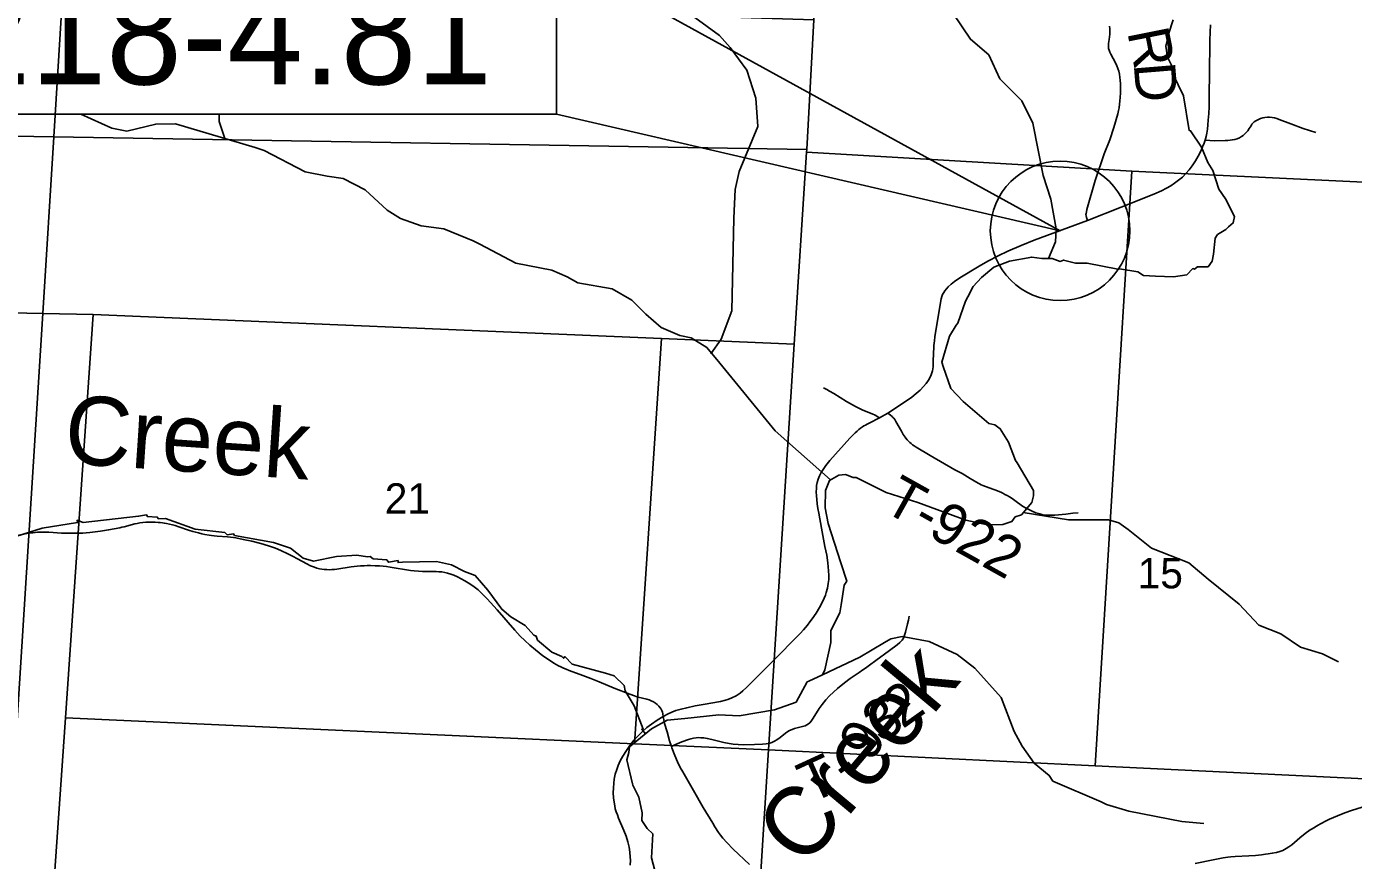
# Model space of a CAD drawing. Extents: x 0 to 34, y 0 to 22.
# Drawn here: x 2.913 to 4.739, y 15.408 to 16.555 of the extents above; entities that cross this region are included whole.
import ezdxf

# ---------------------------------------------------------------- set-up
doc = ezdxf.new("R2010")
doc.units = 0
for name, color, linetype in [('Default', 7, 'Continuous'), ('GM_X_County_Road', 7, 'Continuous'), ('GM_X_Minor_River', 7, 'Continuous'), ('GM_X_Minor_River_Text', 7, 'Continuous'), ('GM_X_Section', 7, 'Continuous'), ('GM_X_Section_Text', 7, 'Continuous'), ('GM_X_State_Route', 7, 'Continuous'), ('GM_X_Township_Road', 7, 'Continuous'), ('GM_X_Township_Road_Text', 7, 'Continuous'), ('TX_P_1', 7, 'Continuous')]:
    doc.layers.add(name, color=color, linetype=linetype)

msp = doc.modelspace()

# ---------------------------------------------------------------- linework, layer by layer
at = {"layer": 'Default'}
for points in [[(2.1, 16.6219), (2.1, 16.4177), (2.9504, 16.4035), (2.9626, 16.5982)], [(2.1, 16.4177), (2.1, 16.178), (2.4468, 16.1708), (2.9352, 16.1608), (2.9504, 16.4035)]]:
    msp.add_lwpolyline(points, close=True, dxfattribs=at)
at = {"layer": 'GM_X_County_Road'}
for points in [[(2.9754, 15.8582), (2.9804, 15.8581), (2.9906, 15.8583), (2.9951, 15.8586), (2.9999, 15.8592), (3.0145, 15.861), (3.0202, 15.8618), (3.0259, 15.8628), (3.0415, 15.8658), (3.0443, 15.8664), (3.0474, 15.8672), (3.0619, 15.871), (3.0653, 15.8717), (3.069, 15.8724), (3.0729, 15.8729), (3.0769, 15.8733), (3.0812, 15.8735), (3.0857, 15.8735), (3.0901, 15.8734), (3.0939, 15.8732), (3.0969, 15.873), (3.0999, 15.8727), (3.1024, 15.8723), (3.1053, 15.8717), (3.1096, 15.8708), (3.1137, 15.8698), (3.1175, 15.8688), (3.1226, 15.8672), (3.136, 15.8626), (3.1419, 15.8607), (3.1457, 15.8596), (3.1497, 15.8586), (3.1541, 15.8576), (3.1583, 15.8567), (3.1642, 15.8557), (3.1676, 15.8551), (3.1712, 15.8547), (3.1752, 15.8543), (3.1893, 15.8532), (3.1936, 15.8527), (3.1975, 15.8522), (3.2009, 15.8517), (3.2112, 15.8498), (3.2231, 15.8472), (3.2352, 15.8442), (3.2457, 15.841), (3.2553, 15.8375), (3.263, 15.8343), (3.2723, 15.8301), (3.2789, 15.8267), (3.2856, 15.823), (3.2984, 15.816), (3.3037, 15.8135), (3.309, 15.8114), (3.3124, 15.8103), (3.3159, 15.8094), (3.3191, 15.8088), (3.3226, 15.8083), (3.326, 15.8082), (3.3294, 15.8081), (3.3332, 15.8082), (3.3367, 15.8085), (3.3397, 15.8089), (3.3597, 15.8119), (3.3636, 15.8124), (3.3677, 15.8129), (3.3724, 15.8133), (3.3776, 15.8136), (3.3818, 15.8137), (3.3862, 15.8137), (3.3925, 15.8136), (3.3986, 15.8134), (3.4035, 15.813), (3.4082, 15.8124), (3.4133, 15.8117), (3.4187, 15.8108), (3.4359, 15.8077), (3.441, 15.807), (3.4464, 15.8063), (3.452, 15.8059), (3.4577, 15.8057), (3.4765, 15.8055), (3.4804, 15.8053), (3.4843, 15.8049), (3.4883, 15.8042), (3.4921, 15.8033), (3.4965, 15.802), (3.5009, 15.8004), (3.506, 15.7981), (3.5107, 15.7957), (3.516, 15.7928), (3.5227, 15.7886), (3.5287, 15.7845), (3.5341, 15.7802), (3.5395, 15.7753), (3.5466, 15.768), (3.5604, 15.7529), (3.5847, 15.7249), (3.5923, 15.7167), (3.5985, 15.7105), (3.6053, 15.7041), (3.613, 15.6977), (3.6233, 15.6897), (3.6309, 15.6843), (3.6383, 15.6795), (3.6448, 15.6758), (3.6481, 15.6743), (3.6518, 15.6726), (3.6555, 15.6711), (3.6595, 15.6695), (3.6785, 15.6626), (3.6892, 15.6585), (3.7009, 15.6538), (3.7214, 15.6452), (3.7431, 15.6366), (3.7493, 15.6344), (3.7518, 15.6336), (3.7545, 15.6328), (3.7662, 15.6299), (3.7694, 15.6289), (3.7725, 15.6278), (3.7755, 15.6263), (3.7781, 15.6246), (3.7805, 15.6227), (3.7827, 15.6204), (3.7845, 15.6182), (3.7859, 15.616), (3.7869, 15.6141), (3.7877, 15.6119), (3.7884, 15.6095), (3.789, 15.6059)], [(2.896, 15.8544), (2.9157, 15.8581), (2.9188, 15.8586), (2.9217, 15.859), (2.925, 15.8594), (2.9282, 15.8596), (2.9325, 15.8598), (2.9369, 15.8598), (2.9404, 15.8598), (2.9438, 15.8596), (2.9613, 15.8585), (2.9754, 15.8582)], [(4.5208, 15.4038), (4.5455, 15.4088), (4.5594, 15.4114), (4.5655, 15.4125), (4.5698, 15.413), (4.5759, 15.4136), (4.5945, 15.4143), (4.6038, 15.4149), (4.6119, 15.4159), (4.6174, 15.4166), (4.6211, 15.4171), (4.6268, 15.418), (4.6324, 15.4191), (4.6372, 15.4204), (4.6413, 15.4219), (4.6458, 15.4242), (4.6496, 15.4265), (4.6536, 15.4295), (4.6648, 15.4392), (4.6721, 15.4449), (4.6791, 15.4499), (4.6816, 15.4516), (4.6899, 15.4567), (4.6931, 15.4584), (4.6958, 15.4599), (4.699, 15.4615), (4.7056, 15.4649), (4.7164, 15.4695), (4.7268, 15.4734), (4.7356, 15.4765), (4.7504, 15.4814)]]:
    msp.add_lwpolyline(points, dxfattribs=at)
at = {"layer": 'GM_X_Minor_River'}
for points in [[(4.3191, 16.2364), (4.3286, 16.2594), (4.3296, 16.2772), (4.3221, 16.3181), (4.3114, 16.3507), (4.2973, 16.4225), (4.2824, 16.453), (4.2655, 16.4703), (4.2519, 16.4836), (4.2367, 16.5167), (4.2116, 16.538), (4.1877, 16.5733), (4.0987, 16.692), (4.0621, 16.7448), (4.0288, 16.766), (4.0171, 16.7789), (4.0136, 16.7881), (4.0099, 16.7928), (3.9283, 16.8675), (3.9083, 16.905)], [(3.8542, 16.1051), (3.8688, 16.1253), (3.8834, 16.1644), (3.886, 16.2916), (3.8881, 16.3311), (3.8932, 16.3562), (3.919, 16.4179), (3.9165, 16.457), (3.9038, 16.4956), (3.8812, 16.5266), (3.8663, 16.5429), (3.8324, 16.5681), (3.7246, 16.6317), (3.6823, 16.6516), (3.5724, 16.6992), (3.485, 16.7682), (3.469, 16.7784), (3.39, 16.8007), (3.374, 16.8086), (3.3423, 16.8328)], [(4.4838, 16.5423), (4.4842, 16.545), (4.4906, 16.5648)], [(4.1944, 16.1473), (4.2048, 16.1776), (4.2082, 16.1837), (4.2153, 16.1977), (4.2267, 16.2099), (4.2437, 16.2244), (4.2652, 16.2324), (4.2958, 16.2382), (4.3098, 16.2364), (4.3238, 16.2364), (4.3348, 16.2322), (4.3397, 16.2341), (4.3559, 16.23), (4.3722, 16.2297), (4.4142, 16.2214), (4.4168, 16.2222), (4.4418, 16.218), (4.4497, 16.2127), (4.466, 16.212), (4.4909, 16.2109), (4.5094, 16.214), (4.5177, 16.2224), (4.52, 16.2217), (4.5238, 16.2247), (4.5385, 16.2247), (4.5442, 16.2327), (4.5461, 16.2422), (4.5483, 16.2643), (4.5513, 16.2692), (4.563, 16.2761), (4.5664, 16.2799), (4.5732, 16.2852), (4.5747, 16.294), (4.5626, 16.3183), (4.5535, 16.3319), (4.5452, 16.3574), (4.538, 16.3684), (4.5293, 16.3893), (4.5145, 16.412), (4.5123, 16.4124), (4.5047, 16.4603), (4.4899, 16.4903), (4.488, 16.5021), (4.4827, 16.5131), (4.4804, 16.5286), (4.4838, 16.5423)], [(4.0192, 15.9318), (3.9431, 15.9991), (3.8666, 16.0922), (3.8491, 16.1137), (3.8272, 16.1273), (3.8118, 16.1304), (3.786, 16.1411), (3.7651, 16.1596), (3.7456, 16.1788), (3.7185, 16.1945), (3.6715, 16.2028), (3.6566, 16.2109), (3.6357, 16.2203), (3.5861, 16.2298), (3.5367, 16.2561), (3.5274, 16.2605), (3.487, 16.277), (3.4558, 16.281), (3.4274, 16.2914), (3.4092, 16.303), (3.3787, 16.3309), (3.3485, 16.3463), (3.3267, 16.3496), (3.2963, 16.3555), (3.2397, 16.385), (3.2274, 16.3888), (3.118, 16.4215), (3.0908, 16.4213), (3.0508, 16.4115), (3.0305, 16.4156), (2.9876, 16.4348)], [(3.1856, 16.4013), (3.1782, 16.4249), (3.1782, 16.4348)], [(3.972, 15.626), (3.9871, 15.6537), (3.9894, 15.6545), (4.0079, 15.6633), (4.0113, 15.6705), (4.0196, 15.7078), (4.0196, 15.7245), (4.032, 15.7485), (4.0335, 15.7599), (4.038, 15.7869), (4.0414, 15.7922), (4.0331, 15.8173), (4.0157, 15.8716), (4.0119, 15.8932), (4.0122, 15.9172), (4.0175, 15.9308), (4.0307, 15.9381), (4.0398, 15.9389), (4.0504, 15.9351), (4.0545, 15.9351), (4.0954, 15.9143), (4.1392, 15.9004), (4.205, 15.8762), (4.2349, 15.8698), (4.2561, 15.8702), (4.2686, 15.8745), (4.2731, 15.8809), (4.2818, 15.8836), (4.2961, 15.9007), (4.2984, 15.9095), (4.2984, 15.9171), (4.2757, 15.955), (4.2734, 15.9581), (4.2639, 15.9835), (4.2526, 16.0021), (4.245, 16.0074), (4.2367, 16.0093), (4.2015, 16.0396), (4.1848, 16.0574), (4.1739, 16.0878), (4.1723, 16.0935), (4.1829, 16.1296), (4.1919, 16.1445), (4.1944, 16.1473)], [(3.7645, 15.5823), (3.7593, 15.5885), (3.7615, 15.5885), (3.749, 15.6208), (3.7365, 15.6413), (3.735, 15.6485), (3.7214, 15.6618), (3.7093, 15.6659), (3.6635, 15.678), (3.6537, 15.6886), (3.6518, 15.6863), (3.6492, 15.6886), (3.6355, 15.6946), (3.6159, 15.7113), (3.614, 15.7166), (3.611, 15.7181), (3.5988, 15.7314), (3.5792, 15.7431), (3.5667, 15.7537), (3.5478, 15.7799), (3.5304, 15.8), (3.5156, 15.8056), (3.4978, 15.8147), (3.477, 15.8192), (3.4302, 15.8183), (3.4241, 15.8179), (3.4241, 15.8206), (3.4109, 15.8183), (3.4086, 15.8217), (3.3897, 15.8232), (3.3859, 15.8262), (3.3822, 15.8258), (3.3674, 15.828), (3.3394, 15.8261), (3.3077, 15.8199), (3.2937, 15.824), (3.2759, 15.8377), (3.2529, 15.8456), (3.1992, 15.8553), (3.1977, 15.8576), (3.189, 15.8561), (3.1856, 15.8591), (3.1451, 15.8639), (3.1043, 15.8783), (3.0944, 15.8782), (3.0929, 15.8805), (3.0793, 15.8812), (3.0782, 15.8835), (3.0672, 15.8816), (2.9909, 15.873), (2.9826, 15.876), (2.9833, 15.873), (2.9346, 15.8653), (2.8896, 15.8511)], [(4.2843, 15.8867), (4.3465, 15.8769), (4.4013, 15.8767), (4.4155, 15.8724), (4.4285, 15.8636), (4.4606, 15.8379), (4.5122, 15.8177), (4.5387, 15.7952), (4.5811, 15.7608), (4.6082, 15.7318), (4.6388, 15.7199), (4.6655, 15.7015), (4.6958, 15.6922), (4.7178, 15.6813)], [(4.0079, 15.6633), (4.0596, 15.6878), (4.0934, 15.708), (4.1019, 15.713), (4.1175, 15.716), (4.1547, 15.7091), (4.1931, 15.6912), (4.2178, 15.6725), (4.254, 15.6323), (4.2719, 15.5854), (4.2826, 15.5653), (4.2993, 15.542), (4.32, 15.525), (4.325, 15.5172), (4.3914, 15.4885), (4.3989, 15.4849), (4.4296, 15.4759), (4.5025, 15.4618), (4.5327, 15.4589)], [(3.7944, 15.6012), (3.8186, 15.6035), (3.8655, 15.6082), (3.8934, 15.6071), (3.9418, 15.6152), (3.972, 15.626)], [(3.7791, 15.3875), (3.7726, 15.4115), (3.7745, 15.4445), (3.7666, 15.4521), (3.7594, 15.4631), (3.7601, 15.4734), (3.7552, 15.495), (3.7472, 15.5117), (3.7465, 15.5136), (3.7389, 15.5463), (3.7415, 15.5566), (3.7426, 15.5642), (3.7729, 15.5893), (3.7944, 15.6012)]]:
    msp.add_lwpolyline(points, dxfattribs=at)
at = {"layer": 'GM_X_Section'}
for points in [[(4.0444, 17.3771), (5.0921, 17.3266), (5.0662, 16.9077), (5.041, 16.4863), (5.0334, 16.328), (4.4335, 16.3564), (3.9862, 16.3827), (3.9864, 16.3863), (3.9959, 16.5649), (4.0188, 16.9784)], [(2.9626, 16.5982), (3.9959, 16.5649), (3.9864, 16.3863), (2.9504, 16.4035)], [(3.9864, 16.3863), (3.9862, 16.3827), (3.9691, 16.1182), (3.7866, 16.126), (3.0046, 16.1593), (2.9352, 16.1608), (2.9504, 16.4035)], [(4.4335, 16.3564), (4.383, 15.5384), (3.9339, 15.5602), (3.9691, 16.1182), (3.9862, 16.3827)], [(5.0334, 16.328), (5.0168, 16.0903), (4.9455, 16.091), (4.9066, 15.513), (4.383, 15.5384), (4.4335, 16.3564)], [(2.9352, 16.1608), (2.8841, 15.3459), (2.3978, 15.3611), (2.4468, 16.1708)], [(3.0046, 16.1593), (2.9664, 15.604), (2.9483, 15.3412), (2.8868, 15.3457), (2.8841, 15.3459), (2.9352, 16.1608)], [(3.7866, 16.126), (3.7495, 15.5685), (2.9664, 15.604), (3.0046, 16.1593)], [(3.9691, 16.1182), (3.9339, 15.5602), (3.7495, 15.5685), (3.7866, 16.126)], [(2.9664, 15.604), (3.7495, 15.5685), (3.9339, 15.5602), (3.9173, 15.2973), (2.9483, 15.3412)], [(3.9339, 15.5602), (4.383, 15.5384), (4.9066, 15.513), (4.889, 15.2523), (3.9173, 15.2973)]]:
    msp.add_lwpolyline(points, close=True, dxfattribs=at)
at = {"layer": 'GM_X_State_Route'}
for points in [[(3.8437, 15.6225), (3.8677, 15.6266), (3.8744, 15.6284), (3.878, 15.6295), (3.8832, 15.6316), (3.8894, 15.6347), (3.8947, 15.6382), (3.8986, 15.6413), (3.9041, 15.6464), (3.9437, 15.6864), (3.9724, 15.7152), (3.9774, 15.7204), (3.9819, 15.7251), (3.9875, 15.7319), (3.9907, 15.7361), (3.9938, 15.7404), (3.9991, 15.7481), (4.004, 15.7561), (4.0076, 15.7627), (4.0105, 15.769), (4.012, 15.7731), (4.0132, 15.7767), (4.0148, 15.7827), (4.016, 15.7889), (4.0166, 15.7945), (4.0168, 15.8002), (4.0165, 15.8064), (4.0153, 15.8176), (4.0139, 15.8281), (4.0114, 15.8402), (4.0066, 15.8651), (4.0028, 15.8859), (4.0018, 15.8922), (4.0008, 15.8985), (4.0001, 15.9047), (3.9998, 15.9096), (3.9995, 15.9151), (3.9996, 15.92), (3.9999, 15.9241), (4.0008, 15.928), (4.0022, 15.9325), (4.0041, 15.9371), (4.0063, 15.9417), (4.0089, 15.9459), (4.0128, 15.9515), (4.0182, 15.9582), (4.0456, 15.989), (4.0493, 15.9929), (4.0528, 15.9964), (4.0555, 15.9989), (4.0579, 16.0009), (4.0602, 16.0026), (4.0629, 16.0045), (4.065, 16.0059), (4.0672, 16.0071), (4.0696, 16.0084), (4.0722, 16.0097), (4.0863, 16.0168), (4.0981, 16.0233), (4.1238, 16.0402), (4.1311, 16.0456), (4.1371, 16.0505), (4.1425, 16.0553), (4.1472, 16.0601), (4.1508, 16.0643), (4.154, 16.0689), (4.1561, 16.0728), (4.1576, 16.0763), (4.1592, 16.0818), (4.1601, 16.0873), (4.1605, 16.0929), (4.1609, 16.1078), (4.1611, 16.1121), (4.1613, 16.1164), (4.1619, 16.1232), (4.1627, 16.1287), (4.1704, 16.1758), (4.1713, 16.1806), (4.1722, 16.1841), (4.1733, 16.1869), (4.1748, 16.1895), (4.1764, 16.192), (4.1786, 16.1945), (4.181, 16.1972), (4.185, 16.201), (4.1898, 16.2048), (4.197, 16.2097), (4.2234, 16.2259), (4.2353, 16.2324), (4.2497, 16.2398), (4.2631, 16.2462), (4.2813, 16.2543), (4.2991, 16.2614), (4.3724, 16.2885), (4.4187, 16.3068), (4.4637, 16.3246), (4.4746, 16.3295), (4.4813, 16.3329), (4.4872, 16.3363), (4.4924, 16.3398), (4.4979, 16.344), (4.5032, 16.3484), (4.5081, 16.3533), (4.5126, 16.3585), (4.5168, 16.364), (4.5213, 16.3708), (4.525, 16.3773), (4.5284, 16.3839), (4.531, 16.3897), (4.533, 16.3948), (4.5343, 16.399), (4.5357, 16.4043), (4.5366, 16.4086), (4.5376, 16.4143), (4.5383, 16.4203), (4.5388, 16.4266), (4.5394, 16.4356), (4.5398, 16.4449), (4.54, 16.4533), (4.5402, 16.4639), (4.5404, 16.4889), (4.5409, 16.5369), (4.5412, 16.5479), (4.5416, 16.5577)], [(3.789, 15.6059), (3.7956, 15.6097), (3.8006, 15.612), (3.8064, 15.6141), (3.8134, 15.6162), (3.8212, 15.6182), (3.8328, 15.6206), (3.8437, 15.6225)], [(3.7433, 15.4014), (3.7437, 15.4082), (3.7436, 15.4126), (3.7431, 15.4195), (3.7419, 15.4263), (3.7402, 15.4336), (3.7377, 15.4414), (3.7348, 15.449), (3.7276, 15.4662), (3.7258, 15.4709), (3.7242, 15.475), (3.7229, 15.4792), (3.7221, 15.483), (3.7214, 15.488), (3.7207, 15.4942), (3.7202, 15.5009), (3.7203, 15.5077), (3.7208, 15.5144), (3.7215, 15.5199), (3.723, 15.5265), (3.7249, 15.533), (3.7271, 15.5388), (3.7298, 15.5449), (3.7333, 15.5515), (3.7382, 15.5593), (3.7429, 15.5661), (3.7486, 15.5733), (3.7542, 15.5796), (3.7603, 15.5856), (3.7662, 15.5908), (3.7729, 15.5957), (3.7807, 15.6009), (3.789, 15.6059)], [(3.8571, 15.4592), (3.844, 15.4809), (3.8305, 15.5044), (3.8159, 15.5297), (3.8123, 15.5361), (3.8085, 15.5439), (3.8048, 15.5524), (3.8009, 15.5628), (3.8002, 15.565), (3.7977, 15.5728), (3.7941, 15.5848), (3.7908, 15.5964), (3.7901, 15.599), (3.7896, 15.6014), (3.789, 15.6059)], [(3.9074, 15.4025), (3.8853, 15.4234), (3.8764, 15.4325), (3.871, 15.4385), (3.8677, 15.4427), (3.8651, 15.4464), (3.8601, 15.4542), (3.8571, 15.4592)]]:
    msp.add_lwpolyline(points, dxfattribs=at)
at = {"layer": 'GM_X_Township_Road'}
for points in [[(4.4027, 16.5559), (4.4032, 16.5522), (4.4035, 16.5485), (4.4034, 16.5449), (4.403, 16.5413), (4.4023, 16.5374), (4.4017, 16.5319), (4.4016, 16.5275), (4.4017, 16.5252), (4.4023, 16.5229), (4.4032, 16.5202), (4.4047, 16.5174), (4.411, 16.5057), (4.4131, 16.5016), (4.4145, 16.4979), (4.4158, 16.4942), (4.4167, 16.4901), (4.4173, 16.4855), (4.4177, 16.4815), (4.418, 16.4766), (4.4181, 16.4703), (4.4179, 16.4639), (4.4172, 16.4529), (4.4167, 16.4485), (4.416, 16.4438), (4.4153, 16.4397), (4.4143, 16.4354), (4.409, 16.4163), (4.4031, 16.3997), (4.3956, 16.3803), (4.3833, 16.3435), (4.3718, 16.3038), (4.371, 16.3006), (4.3706, 16.2983), (4.3705, 16.2966), (4.3706, 16.2948), (4.3712, 16.2926), (4.3724, 16.2885)], [(4.5343, 16.399), (4.5474, 16.3984), (4.562, 16.3986), (4.5658, 16.3987), (4.5688, 16.399), (4.5717, 16.3994), (4.5751, 16.4001), (4.5785, 16.4011), (4.5816, 16.4025), (4.5846, 16.4041), (4.5866, 16.4056), (4.5887, 16.4074), (4.5913, 16.4099), (4.5932, 16.4121), (4.5952, 16.4151), (4.5976, 16.4189), (4.5989, 16.4209), (4.6002, 16.4226), (4.6019, 16.4241), (4.604, 16.4256), (4.607, 16.4272), (4.6104, 16.4288), (4.6138, 16.4299), (4.6167, 16.4305), (4.6201, 16.4309), (4.6232, 16.4308), (4.6266, 16.4304), (4.6301, 16.4297), (4.6331, 16.4288), (4.6361, 16.4277), (4.6522, 16.4218), (4.6691, 16.4153), (4.6778, 16.4124), (4.6866, 16.4098)], [(4.0094, 16.0583), (4.0139, 16.056), (4.0178, 16.0539), (4.0237, 16.0505), (4.041, 16.0395), (4.0534, 16.0328), (4.0628, 16.028), (4.0775, 16.0219), (4.0794, 16.0211), (4.0815, 16.0201), (4.0832, 16.0189), (4.0863, 16.0168)], [(4.0981, 16.0233), (4.1016, 16.0207), (4.1038, 16.0189), (4.105, 16.0177), (4.1062, 16.0164), (4.1074, 16.0148), (4.1089, 16.0122), (4.1165, 15.9985), (4.1191, 15.9943), (4.1205, 15.9921), (4.1218, 15.9905), (4.1229, 15.989), (4.1246, 15.9869), (4.1264, 15.985), (4.128, 15.9833), (4.13, 15.9816), (4.132, 15.98), (4.1342, 15.9784), (4.1369, 15.9766), (4.156, 15.965), (4.19, 15.9457), (4.2004, 15.9405), (4.2114, 15.9336), (4.2222, 15.9271), (4.2241, 15.9261), (4.2261, 15.925), (4.2285, 15.924), (4.2425, 15.9189), (4.2467, 15.9174), (4.2498, 15.9162), (4.2535, 15.9146), (4.2561, 15.9132), (4.259, 15.9117), (4.2621, 15.91), (4.2654, 15.9081), (4.2689, 15.9058), (4.2727, 15.9031), (4.2833, 15.8956), (4.2873, 15.8931), (4.2917, 15.8907), (4.2964, 15.8885), (4.3017, 15.8864), (4.3071, 15.8848), (4.3113, 15.8837), (4.3144, 15.8832), (4.3173, 15.883), (4.3218, 15.8829), (4.3278, 15.8832), (4.3426, 15.8847), (4.3526, 15.8858), (4.3598, 15.8865)], [(3.8002, 15.565), (3.8047, 15.5669), (3.8143, 15.571), (3.8237, 15.5745), (3.827, 15.5755), (3.8306, 15.5763), (3.834, 15.5768), (3.8373, 15.577), (3.8407, 15.5769), (3.8449, 15.5765), (3.8495, 15.5759), (3.8557, 15.5746), (3.8725, 15.5702), (3.8798, 15.5687), (3.8853, 15.5679), (3.892, 15.5675), (3.8995, 15.5673), (3.9144, 15.5675), (3.9255, 15.5678), (3.9304, 15.5683), (3.934, 15.569), (3.9382, 15.5703), (3.9422, 15.572), (3.9453, 15.5738), (3.9497, 15.577), (3.955, 15.5814), (3.959, 15.5844), (3.9627, 15.5867), (3.9661, 15.5884), (3.9696, 15.5897), (3.9751, 15.591), (3.9805, 15.5921), (3.984, 15.5932), (3.9867, 15.5945), (3.9888, 15.5958), (3.9906, 15.5974), (3.9926, 15.5996), (3.9954, 15.6037), (4.0035, 15.6169), (4.0075, 15.6225), (4.0125, 15.6288), (4.0176, 15.6344), (4.023, 15.6396), (4.0286, 15.6444), (4.0384, 15.6522), (4.0463, 15.6582), (4.0584, 15.6667), (4.0636, 15.6702), (4.0671, 15.6727), (4.0707, 15.6752), (4.0727, 15.6767), (4.0812, 15.6829), (4.1002, 15.6969), (4.1107, 15.7046), (4.1145, 15.7078), (4.1174, 15.7109), (4.1193, 15.714), (4.1206, 15.7167), (4.1224, 15.7219), (4.125, 15.7334), (4.1262, 15.7388), (4.1271, 15.7439)]]:
    msp.add_lwpolyline(points, dxfattribs=at)
at = {"layer": 'TX_P_1'}
for points in [[(2.3381, 16.6555), (3.6423, 16.6555), (3.6423, 16.4348), (2.3381, 16.4348)], [(3.6423, 16.6555), (4.3349, 16.2743), (3.6423, 16.4348)]]:
    msp.add_lwpolyline(points, close=True, dxfattribs=at)
msp.add_circle((4.3349, 16.2743), 0.096, dxfattribs=at)

# ---------------------------------------------------------------- texts
at = {"layer": 'GM_X_Minor_River_Text'}
for height, rotation, p in [(0.09469, 356.1515, (2.9633, 15.9546)), (0.0947, 50.1344, (3.9829, 15.3955))]:
    msp.add_text('Creek', height=height, rotation=rotation, dxfattribs=at).set_placement(p)
at = {"layer": 'GM_X_Section_Text'}
for s, p in [('21', (3.4058, 15.8851)), ('15', (4.4416, 15.7824))]:
    msp.add_text(s, height=0.04186, rotation=0, dxfattribs=at).set_placement(p)
at = {"layer": 'GM_X_Township_Road_Text'}
for s, height, rotation, p in [('R', 0.0568, 281.2384, (4.4272, 16.5481)), ('D', 0.0568, 274.719, (4.4361, 16.504)), ('T-922', 0.05682, 330.8119, (4.0887, 15.8905)), ('2', 0.0568, 35.3991, (4.1181, 15.5882)), ('3', 0.0568, 36.3172, (4.0901, 15.5676)), ('9', 0.0568, 58.8682, (4.0759, 15.542)), ('T', 0.0568, 24.7018, (3.9917, 15.4857)), ('-', 0.0568, 37.6277, (4.0422, 15.5107))]:
    msp.add_text(s, height=height, rotation=rotation, dxfattribs=at).set_placement(p)
at = {"layer": 'TX_P_1'}
msp.add_text('GAL-218-4.81', height=0.14, dxfattribs=at).set_placement((2.3774, 16.4758))

doc.saveas('drawing.dxf')
